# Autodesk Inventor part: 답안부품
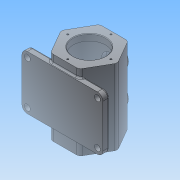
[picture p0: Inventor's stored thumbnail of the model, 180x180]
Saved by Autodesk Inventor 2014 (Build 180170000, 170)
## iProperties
Created: 2021-06
Part Number: 답안부품
Material: 일반
Document SubType Name: Modeling
Designer: net
Density: 1 g/cm^3
Appearance: 기본값
Author: net
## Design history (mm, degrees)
sketch "스케치1" dims "d0" = 105
  geometry: L1 (52.5, 0)-(26.25, -45.466); L2 (26.25, -45.466)-(-26.25, -45.466); L3 (-26.25, -45.466)-(-52.5, 0); L4 (-52.5, 0)-(-26.25, 45.466); L5 (-26.25, 45.466)-(26.25, 45.466); L6 (26.25, 45.466)-(52.5, 0); 4 further points
  constraints: 12 end point, 2 coincident, 1 horizontal alignment, 1 midpoint, 1 vertical alignment, 15 other
  dimensions: "d1" = 52.5 distance of L4.end L5.end (derived)
extrude "돌출1" new body sketch "스케치1" stored distance "d2" = 140; taper "d3" = 0 deg
sketch "스케치3"
  geometry: L1 (45.466, -70)-(-45.466, -70) reference; L2 (-45.466, -70)-(-45.466, 70) reference; L3 (-45.466, 70)-(45.466, 70) reference; L4 (45.466, 70)-(45.466, -70) reference; L5 (45.466, -70)-(-45.466, -70) reference; L6 (-45.466, -70)-(-45.466, 70) reference; L7 (-45.466, 70)-(45.466, 70) reference; L8 (45.466, 70)-(45.466, -70) reference; L9 (45.466, -70)-(-45.466, -70) reference; L10 (-45.466, -70)-(-45.466, 70) reference; L11 (-45.466, 70)-(45.466, 70) reference; L12 (45.466, 70)-(45.466, -70) reference; L13 (45.466, 70)-(0, 70) reference; L14 (45.466, 70)-(45.466, -70) reference; L15 (0, -70)-(45.466, -70) reference; L16 (-45.466, -70)-(0, -70) reference; L17 (-45.466, 70)-(-45.466, -70) reference; L18 (0, 70)-(-45.466, 70) reference; L19 (45.466, -70)-(-45.466, -70) reference; L20 (-45.466, -70)-(-45.466, 70) reference; L21 (-45.466, 70)-(45.466, 70) reference; L22 (45.466, 70)-(45.466, -70) reference; L23 (0, -70)-(0, 70); L24 (30, -70)-(30, -58); L25 (30, -58)-(37.5, -58); L26 (37.5, -58)-(37.5, 58); L27 (37.5, 58)-(30, 58); L28 (30, 58)-(30, 70); 1 further point
  constraints: 12 end point, 3 parallel, 3 perpendicular, 2 point on line
  dimensions: "d4" = 60 diameter of L24 L23; "d5" = 12 distance of L24.start L24.end; "d6" = 12 distance of L27.end L28.end; "d7" = 60 diameter of L28 L23; "d8" = 75 diameter of L26 L23
revolve "회전1" sketch "스케치3" stored, may be unused: angle "d9" = 90 deg
node "작업 평면1"
sketch "스케치5"
  geometry: L1 (52.5, 0)-(0, 0) reference; L2 (0, 140)-(52.5, 140) reference; L3 (26.25, 140)-(26.25, 0); L4 (78.75, 0)-(52.5, 0) reference; C1 r 20 at (26.25, 100); C2 r 20 at (26.25, 40); 1 further point
  constraints: 2 centre point, 2 end point, 2 midpoint, 2 point on line
  dimensions: "d18" = 40 diameter of C1; "d19" = 40 distance from line of L2 C1.centre; "d20" = 60 distance of C2.centre C1.centre; "d21" = 40 diameter of C2
extrude "돌출3" join sketch "스케치5" distance "d22" = 7; taper "d23" = 0 deg
sketch "스케치6"
  geometry: C1 r 20 at (0, 0) reference; C2 r 20 at (0, -60) reference; C3 r 15 at (0, 0); C4 r 15 at (0, -60); 1 further point
  constraints: 2 centre point, 2 coincident
  dimensions: "d24" = 30 diameter of C3; "d25" = 30 diameter of C4
extrude "돌출4" cut sketch "스케치6" distance "d26" = 8; taper "d27" = 0 deg
sketch "스케치7"
  geometry: C1 r 15 at (0, 0) reference; C2 r 15 at (0, -60) reference; C3 r 12.5 at (0, 0); C4 r 12.5 at (0, -60); 1 further point
  constraints: 2 centre point, 2 coincident
  dimensions: "d28" = 25 diameter of C3; "d29" = 25 diameter of C4
extrude "돌출5" cut sketch "스케치7" stored distance "d30" = 8; taper "d31" = 0 deg
fillet "모깎기2" dims "d39" = 8
fillet "모깎기4" dims "d41" = 5
fillet "모깎기5" dims "d42" = 3
chamfer "모따기1" distance "d43" = 1; stored, may be unused: second distance "d44" = 2, angle "d45" = 45 deg
node "작업 평면2"
sketch "스케치12"
  geometry: L1 (-28.559, -70)-(-50.191, -70) reference; L2 (21.631, -70)-(-21.631, -70) reference; L3 (50.191, -70)-(28.559, -70) reference; L4 (-75, -45)-(75, -45); L5 (75, -45)-(75, 55); L6 (75, 55)-(-75, 55); L7 (-75, 55)-(-75, -45); L8 (-50.191, 70)-(-28.559, 70) reference; L9 (-21.631, 70)-(21.631, 70) reference; L10 (28.559, 70)-(50.191, 70) reference; 2 further points
  constraints: 8 end point, 2 parallel, 1 horizontal, 1 midpoint, 1 perpendicular, 1 vertical alignment
  dimensions: "d62" = 25 distance between parallel lines of L4 L1; "d63" = 15 distance between parallel lines of L8 L6; "d64" = 150 distance between parallel lines of L5 L7
extrude "돌출7" join sketch "스케치12" distance "d65" = 12; taper "d66" = 0 deg
fillet "모깎기6" dims "d67" = 10
sketch "스케치13"
  geometry: L1 (-75, 35)-(-75, -45) reference; L2 (-65, -55)-(-30.561, -55) reference; L3 (-30.561, 45)-(-30.561, -55) reference; L4 (-30.561, 45)-(-65, 45) reference; C1 r 5.5 at (-65, 35); C2 r 5.5 at (-65, -45); C3 r 5.5 at (65, 35); C4 r 5.5 at (65, -45); A1 r 10 centre (65, 35) between (75, 35) and (65, 45) reference; A2 r 10 centre (65, -45) between (65, -55) and (75, -45) reference; A3 r 10 centre (-65, 35) between (-65, 45) and (-75, 35) reference; A4 r 10 centre (-65, -45) between (-75, -45) and (-65, -55) reference; 1 further point
  constraints: 4 centre point, 4 coincident
  dimensions: "d68" = 11 diameter of C1; "d69" = 11 diameter of C2; "d70" = 11 diameter of C4; "d71" = 11 diameter of C3
extrude "돌출8" cut sketch "스케치13" distance "d72" = 12; taper "d73" = 0 deg
fillet "모깎기7" dims "d74" = 3
sketch "스케치14"
  geometry: L1 (72, 35)-(72, -45) reference; L2 (65, 45)-(32.293, 45) reference; 2 further points
  constraints: 1 other
  dimensions: "d75" = 14 distance from line of L1 point (58, -5); "d76" = 50 distance from line of L2 point (58, -5)
feature "엠보싱1" sketch "스케치14" dims "d77" = 0.5, "d78" = 0
sketch "스케치15" dims "d79" = 80
  geometry: C1 r 30 at (0, 0) reference; 2 further points
  constraints: 2 vertical alignment, 1 coincident, 2 other
hole "구멍2" sketch "스케치15" at (0, 40) diameter "d80" = 3.242; stored, may be unused: countersink angle "d84" = 90 deg, drill point angle "d86" = 118 deg; dims "d81" = 8, "d82" = 4, "d83" = 2, "d85" = 10
sketch "스케치16" dims "d90" = 80
  geometry: L1 (21.631, 45.466)-(-21.631, 45.466) reference; L2 (0, 0)-(0, 95.284); L3 (0, 0)-(-64.838, 64.838); C1 r 30 at (0, 0) reference; 2 further points
  constraints: 4 end point, 1 coincident, 1 perpendicular, 1 point on line, 3 other
  dimensions: "d91" = 45 deg angle of L2 L3
hole "구멍3" sketch "스케치16" at (-28.284, 28.284) diameter "d92" = 3.242; stored, may be unused: countersink angle "d96" = 90 deg, drill point angle "d98" = 118 deg; dims "d93" = 8, "d94" = 4, "d95" = 2, "d97" = 10
chamfer "모따기2" distance "d102" = 1; stored, may be unused: second distance "d103" = 2, angle "d104" = 45 deg
node "솔리드1"
pattern_circular "원형 패턴2" dims angle "d88" = 360 deg
pattern_circular "원형 패턴3" dims angle "d100" = 360 deg
node "투영된 루프1"
node "투영된 루프4"
node "절단 모서리 투영2"
node "절단 모서리 투영3"
node "절단 모서리 투영4"
node "절단 모서리 투영5"
